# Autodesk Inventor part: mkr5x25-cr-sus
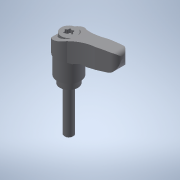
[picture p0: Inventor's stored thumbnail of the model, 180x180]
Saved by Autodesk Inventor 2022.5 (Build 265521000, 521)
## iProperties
Created: 2017-09
Part Number: mkr5x25-cr-sus
Material: 一般
Document SubType Name: Modeling
Designer: imaocorp
Density: 1 g/cm^3
Appearance: 既定
Author: imaocorp
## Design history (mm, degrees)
node "mkr5x25-cr-sus.x_t1"
node "mkr5x25-cr-sus"
node "Base1"
